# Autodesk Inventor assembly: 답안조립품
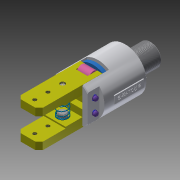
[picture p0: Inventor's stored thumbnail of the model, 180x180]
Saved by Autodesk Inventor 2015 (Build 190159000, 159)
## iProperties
Created: 2019-02
Part Number: 답안조립품
Document SubType Name: Assembly
Designer: now
Author: now
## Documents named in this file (11)
- C:\Users\now\Desktop\490207V1017\답안조립품.iam
- C:\Users\now\Desktop\490207V1017\E-링.ipt
- C:\Users\now\Desktop\490207V1017\O-링.ipt
- C:\Users\now\Desktop\490207V1017\가이드핀.ipt
- C:\Users\now\Desktop\490207V1017\본체.ipt
- C:\Users\now\Desktop\490207V1017\부시.ipt
- C:\Users\now\Desktop\490207V1017\스프링.ipt
- C:\Users\now\Desktop\490207V1017\평행핀 6x28.ipt
- C:\Users\now\Desktop\490207V1017\피스톤.ipt
- C:\Users\now\Desktop\490207V1017\핀.ipt
- C:\Users\now\Desktop\490207V1017\핑거.ipt
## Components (13 placed, 6 different names)
1. O-링:1
2. 가이드핀:1
3. 피스톤:1 — 각도:1
4. 핀:1
5. 핑거:1
6. 핑거:2
7. 핀:2
8. E-링:2
9. O-링:2
10. 가이드핀:2
11. E-링:3
12. E-링:4
13. E-링:5
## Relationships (1: Angle 1)
- 각도:1 [Angle]: 피스톤:1
